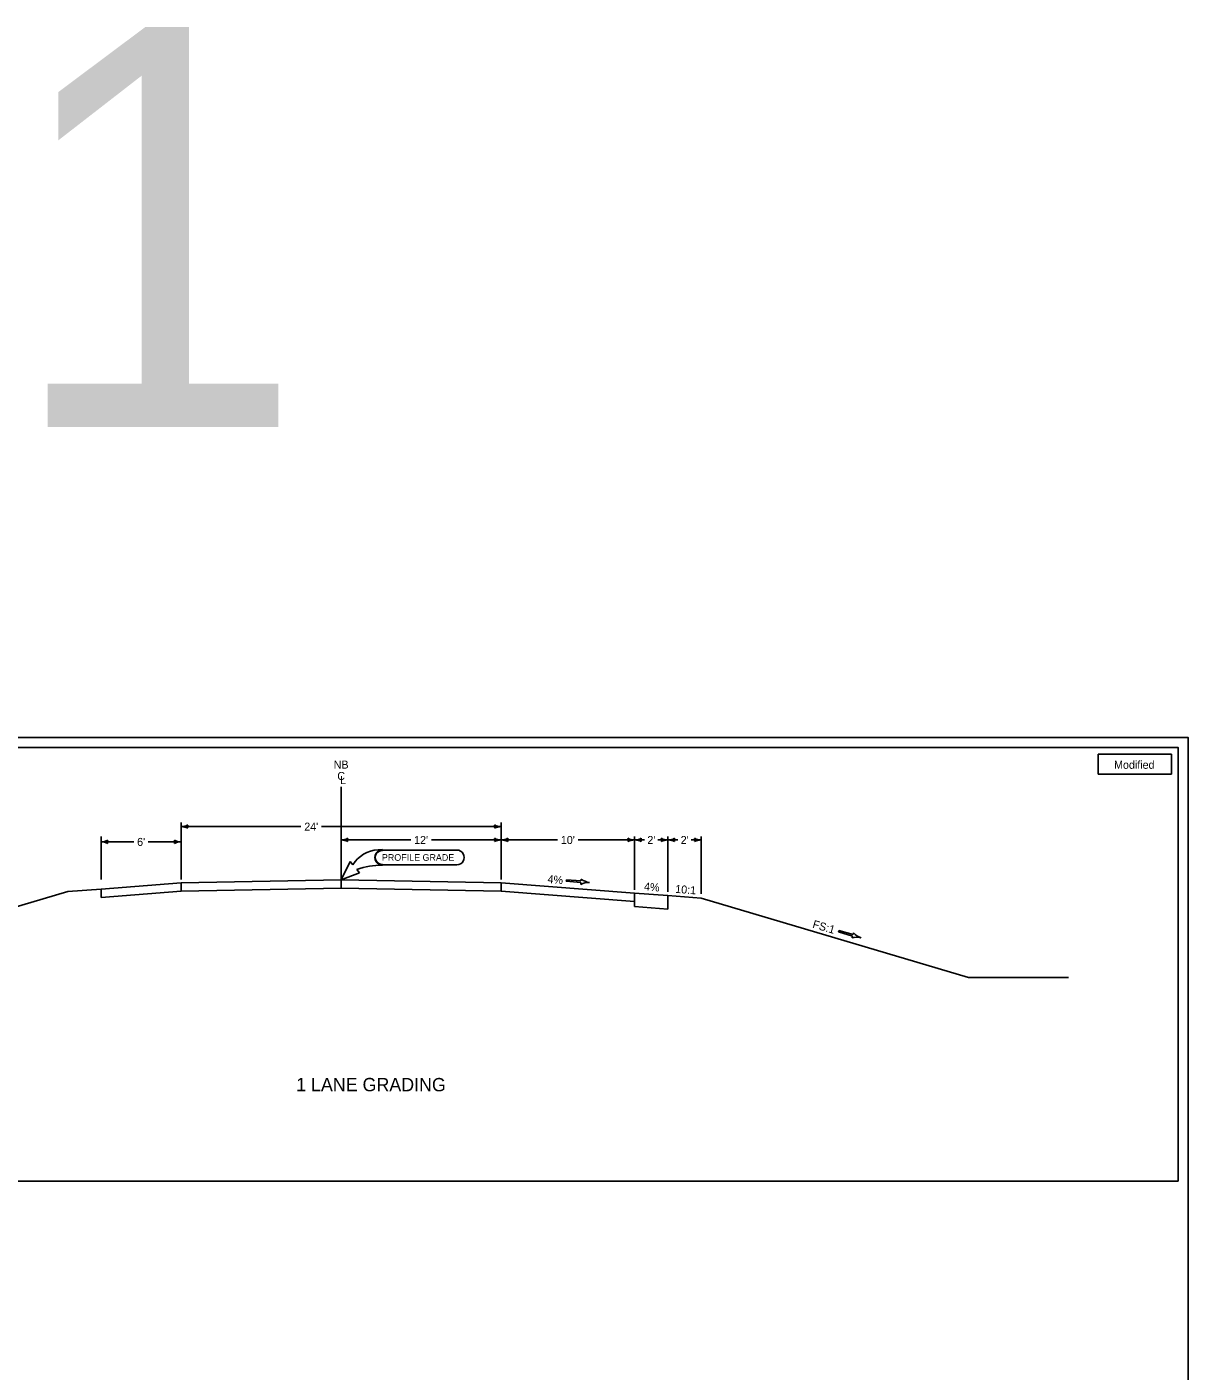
# Model space of a CAD drawing. Extents: x 10133 to 81668, y 6979 to 11018.
# Drawn here: x 11526 to 13268, y 8994 to 11009 of the extents above; entities that cross this region are included whole.
import ezdxf

# ---------------------------------------------------------------- set-up
doc = ezdxf.new("R2010")
doc.units = 0
for name, color, linetype in [('brgPreRevetmentShaded', 7, 'Continuous'), ('brgPreStructureAlternateA', 7, 'Continuous'), ('brgPreStructureNew', 7, 'Continuous'), ('brgRebarEpoxyA', 7, 'Continuous'), ('DisFieldPointElev', 7, 'Continuous'), ('dsnCellElements', 7, 'Continuous'), ('dsnShtPlotShapeBatchPrint', 7, 'Continuous'), ('dsnStdShading', 7, 'Continuous'), ('Level 11', 7, 'Continuous'), ('Print Border', 7, 'Continuous'), ('Shape', 7, 'Continuous')]:
    doc.layers.add(name, color=color, linetype=linetype)

msp = doc.modelspace()

# ---------------------------------------------------------------- linework, layer by layer
at = {"layer": 'brgPreRevetmentShaded'}
for p, q in [((11637.6, 9716.8), (11757.6, 9726)), ((11637.6, 9716.8), (11637.6, 9704.3)), ((11637.6, 9704.3), (11757.6, 9713.4)), ((11997.6, 9730.8), (11757.6, 9726)), ((11757.6, 9726), (11757.6, 9713.4)), ((11997.6, 9718.2), (11757.6, 9713.4)), ((11997.6, 9730.8), (12237.6, 9726)), ((11997.6, 9718.2), (12237.6, 9713.4)), ((12437.6, 9710.7), (12237.6, 9726)), ((12237.6, 9726), (12237.6, 9713.4)), ((12437.6, 9698.2), (12237.6, 9713.4))]:
    msp.add_line(p, q, dxfattribs=at)
at = {"layer": 'brgPreStructureAlternateA'}
for p, q in [((11587.6, 9713), (11186.9, 9594)), ((11637.6, 9716.8), (11587.6, 9713)), ((12938.2, 9584.1), (13088.2, 9584.1))]:
    msp.add_line(p, q, dxfattribs=at)
at = {"layer": 'brgPreStructureNew'}
for p, q in [((11997.6, 9718.2), (11997.6, 9869.8)), ((11757.6, 9816.3), (11757.6, 9731)), ((12237.6, 9816.3), (12237.6, 9731)), ((11637.6, 9795.3), (11637.6, 9731)), ((11757.6, 9810.3), (11937.3, 9810.3)), ((11968.3, 9810.3), (12237.6, 9810.3)), ((12437.6, 9795.3), (12437.6, 9715.7)), ((12487.6, 9795.3), (12487.6, 9712.6)), ((12537.6, 9795.3), (12537.6, 9709.6)), ((11637.6, 9787.4), (11686.7, 9787.4)), ((11757.6, 9787.4), (11708.4, 9787.4)), ((12102, 9790.3), (11997.6, 9790.3)), ((12237.6, 9790.3), (12133.1, 9790.3)), ((12237.6, 9790.3), (12322, 9790.3)), ((12353.1, 9790.3), (12437.6, 9790.3)), ((12437.6, 9790.3), (12452.6, 9790.3)), ((12487.6, 9790.3), (12472.6, 9790.3)), ((12487.6, 9790.3), (12502.6, 9790.3)), ((12537.6, 9790.3), (12522.6, 9790.3))]:
    msp.add_line(p, q, dxfattribs=at)
for centre, radius, start, end in [((11757.6, 9831.6), 21.3, 270, 298.0725), ((11757.6, 9789.1), 21.3, 61.9275, 90), ((11775.4, 9810.3), 8.21, 162.2666, 197.7334), ((12219.7, 9810.3), 8.21, 342.2666, 17.7333), ((12237.6, 9831.6), 21.3, 241.9275, 270), ((12237.6, 9789.1), 21.3, 90, 118.0725), ((11637.6, 9808.7), 21.3, 270, 298.0725), ((11637.6, 9766.2), 21.3, 61.9275, 90), ((11655.4, 9787.4), 8.21, 162.2666, 197.7334), ((11739.7, 9787.4), 8.21, 342.2666, 17.7334), ((11757.6, 9808.7), 21.3, 241.9275, 270), ((11757.6, 9766.2), 21.3, 90, 118.0725), ((11997.6, 9811.6), 21.3, 270, 298.0725), ((11997.6, 9769.1), 21.3, 61.9275, 90), ((12015.4, 9790.3), 8.21, 162.2666, 197.7334), ((12219.7, 9790.3), 8.21, 342.2667, 17.7334), ((12237.6, 9811.6), 21.3, 241.9275, 270), ((12237.6, 9769.1), 21.3, 90, 118.0725), ((12237.6, 9811.6), 21.3, 270, 298.0725), ((12237.6, 9769.1), 21.3, 61.9275, 90), ((12255.4, 9790.3), 8.21, 162.2666, 197.7334), ((12419.7, 9790.3), 8.21, 342.2667, 17.7334), ((12437.6, 9811.6), 21.3, 241.9275, 270), ((12437.6, 9769.1), 21.3, 90, 118.0725), ((12437.6, 9811.6), 21.3, 270, 298.0725), ((12437.6, 9769.1), 21.3, 61.9275, 90), ((12455.4, 9790.3), 8.21, 162.2666, 197.7334), ((12469.7, 9790.3), 8.21, 342.2666, 17.7334), ((12487.6, 9811.6), 21.3, 241.9275, 270), ((12487.6, 9769.1), 21.3, 90, 118.0725), ((12487.6, 9811.6), 21.3, 270, 298.0725), ((12487.6, 9769.1), 21.3, 61.9275, 90), ((12505.4, 9790.3), 8.21, 162.2666, 197.7334), ((12519.7, 9790.3), 8.21, 342.2666, 17.7334), ((12537.6, 9811.6), 21.3, 241.9275, 270), ((12537.6, 9769.1), 21.3, 90, 118.0725)]:
    msp.add_arc(centre, radius, start, end, dxfattribs=at)
at = {"layer": 'brgRebarEpoxyA'}
for p, q in [((12437.6, 9710.7), (12437.6, 9690.5)), ((12487.6, 9686.7), (12487.6, 9706.9)), ((12437.6, 9690.5), (12487.6, 9686.7))]:
    msp.add_line(p, q, dxfattribs=at)
at = {"layer": 'DisFieldPointElev'}
for p, q in [((12487.6, 9706.9), (12537.6, 9703.1)), ((12537.6, 9703.1), (12938.2, 9584.1))]:
    msp.add_line(p, q, dxfattribs=at)
at = {"layer": 'dsnCellElements'}
for p, q in [((13132.5, 9889), (13132.5, 9919)), ((13132.5, 9919), (13242.5, 9919)), ((13242.5, 9919), (13242.5, 9889)), ((13242.5, 9919), (13242.5, 9889)), ((13242.5, 9889), (13132.5, 9889))]:
    msp.add_line(p, q, dxfattribs=at)
msp.add_lwpolyline([(10147.5, 9929), (13252.5, 9929), (13252.5, 9279), (10147.5, 9279), (10147.5, 9929)], dxfattribs=at)
at = {"layer": 'dsnStdShading'}
for p, q in [((12052.9, 9775.6), (12059.4, 9775.9)), ((12059.4, 9775.9), (12059.4, 9774.6)), ((12059.4, 9775.2), (12170.9, 9775.2)), ((11997.6, 9730.8), (12011.3, 9758.1)), ((12011.3, 9758.1), (12015.2, 9753.3)), ((12059.4, 9753.6), (12059.4, 9752.4)), ((12025.1, 9741), (11997.6, 9730.8)), ((12021, 9746.1), (12025.1, 9741)), ((12059.4, 9753), (12171, 9753)), ((12335.3, 9730.8), (12335.1, 9728.4)), ((12335.1, 9728.4), (12357, 9726.5)), ((12357.2, 9728.9), (12335.3, 9730.8)), ((12357, 9726.5), (12356.8, 9723.7)), ((12357.5, 9731.7), (12357.2, 9728.9)), ((12369.8, 9726.6), (12369.8, 9726.6)), ((12744, 9654.7), (12743.3, 9652.4)), ((12743.3, 9652.4), (12764.5, 9646.2)), ((12765.1, 9648.5), (12744, 9654.7)), ((12764.5, 9646.2), (12763.7, 9643.5)), ((12765.9, 9651.2), (12765.1, 9648.5)), ((12777, 9643.8), (12777, 9643.8))]:
    msp.add_line(p, q, dxfattribs=at)
for centre, start, end in [((12368.7, 9700.8), 87.4355, 117.4656), ((12373.1, 9752.2), 232.7015, 262.7315), ((12770.8, 9618.8), 76.1032, 106.1333), ((12785.3, 9668.3), 221.3692, 251.3992)]:
    msp.add_arc(centre, 25.8, start, end, dxfattribs=at)
for centre, major_axis, start_param, end_param in [((12056, 9727.5), (-48.4, 0), 4.776871, 5.71778), ((12059.4, 9764.1), (-11.2, 0), 4.712389, 7.853982), ((12059.4, 9764.1), (10.6, 0), 1.570796, 4.712389), ((12170.9, 9764.1), (11.2, 0), 4.712389, 7.853982), ((12057.5, 9645.6), (-107.3, 0), 4.694293, 5.059134)]:
    msp.add_ellipse(centre, major_axis=major_axis, ratio=0.995025, start_param=start_param, end_param=end_param, dxfattribs=at)
at = {"layer": 'Level 11'}
msp.add_lwpolyline([(10132.5, 9944), (13267.5, 9944), (13267.5, 7924), (10132.5, 7924)], close=True, dxfattribs=at)
at = {"layer": 'Shape'}
msp.add_line((12487.6, 9706.9), (12437.6, 9710.7), dxfattribs=at)

# ---------------------------------------------------------------- texts
at = {"layer": 'brgPreStructureNew'}
for s, p in [("24'", (11942.3, 9804.3)), ("6'", (11691.7, 9781.4)), ("12'", (12107, 9784.3)), ("10'", (12327, 9784.3)), ("2'", (12456.7, 9784.3)), ("2'", (12506.7, 9784.3))]:
    msp.add_text(s, height=12, dxfattribs=at).set_placement(p)
at = {"layer": 'dsnShtPlotShapeBatchPrint'}
msp.add_text('Modified', height=12, dxfattribs=at).set_placement((13156.5, 9897))
at = {"layer": 'dsnStdShading'}
for s, height, p in [('NB', 12, (11986.4, 9897.3)), ('C', 12, (11991.8, 9880.3)), ('L', 12, (11996.2, 9874.1)), ('PROFILE GRADE', 10, (12058.7, 9759.1))]:
    msp.add_text(s, height=height, dxfattribs=at).set_placement(p)
for s, height, rotation, p in [('4%', 12, 355.0835, (12306.7, 9726)), ('4%', 12, 355.6329, (12451.4, 9714.7)), ('10:1', 12, 355.6329, (12498.2, 9711.1)), ('FS:1', 12, 343.7512, (12703.5, 9659)), ('1 LANE GRADING', 20, 359.9583, (11930.1, 9413.7))]:
    msp.add_text(s, height=height, rotation=rotation, dxfattribs=at).set_placement(p)
at = {"layer": 'Print Border'}
msp.add_text('1', height=600, dxfattribs=at).set_placement((11496.6, 10409.2))

doc.saveas('drawing.dxf')
